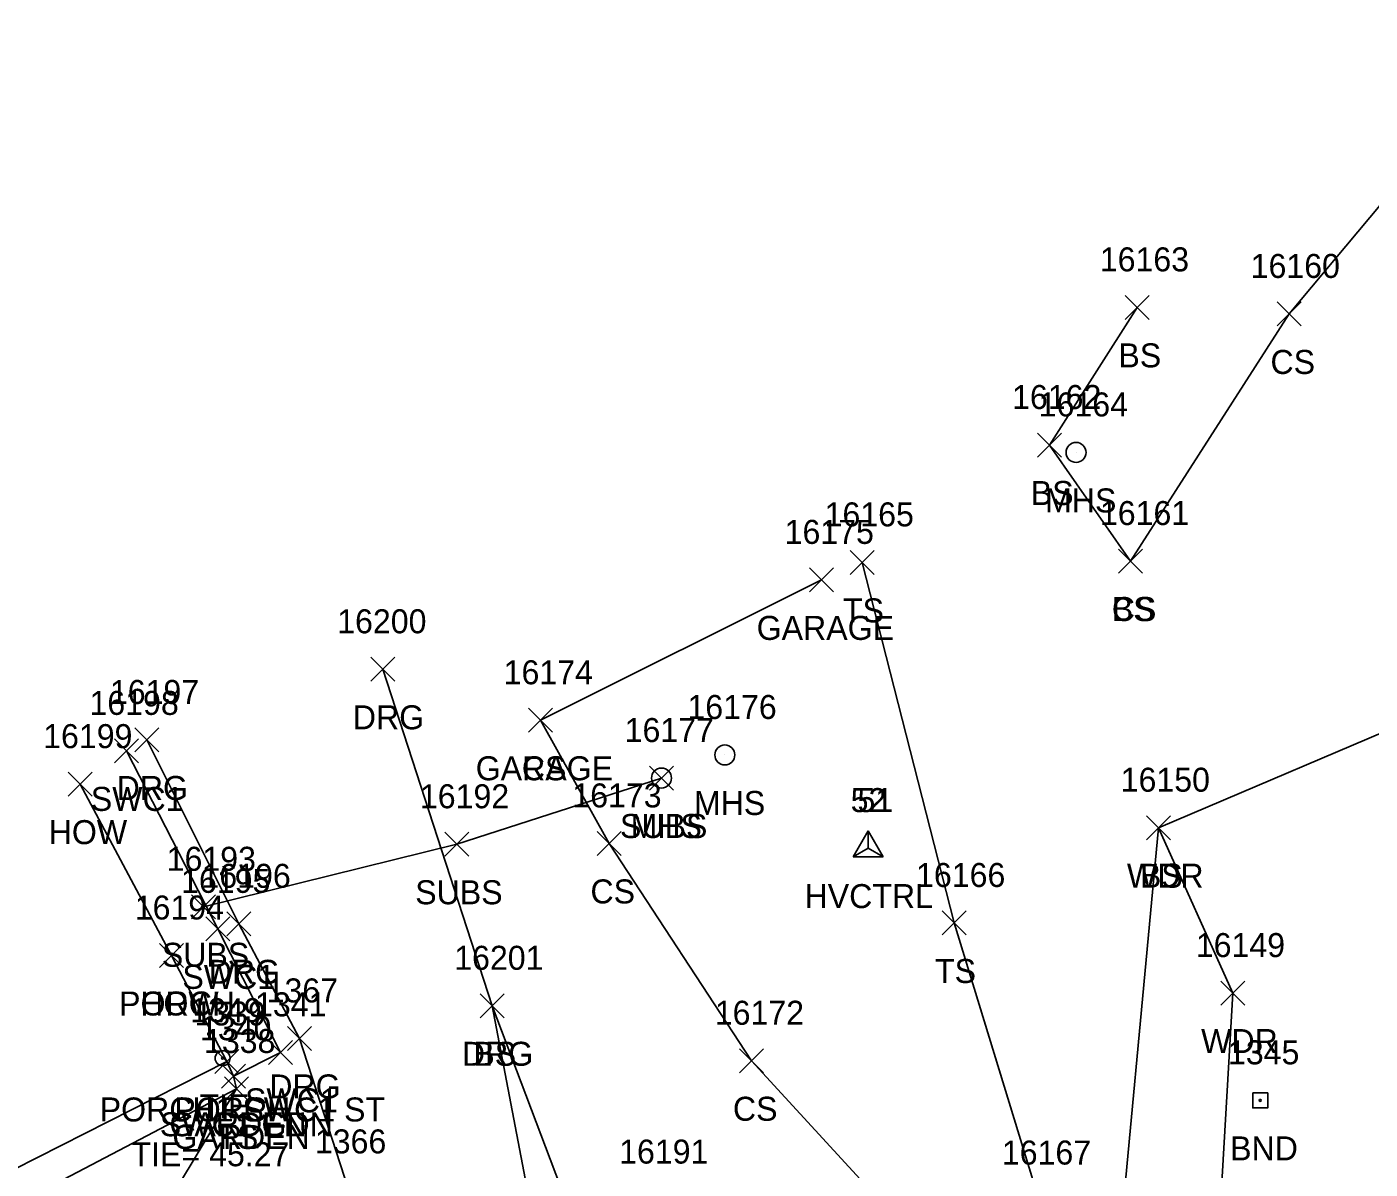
# Model space of a CAD drawing. Extents: x 1606530 to 1613020, y 784959 to 789666.
# Drawn here: x 1609059.8 to 1609171.7, y 788467.6 to 788562.7 of the extents above; entities that cross this region are included whole.
import ezdxf

# ---------------------------------------------------------------- set-up
doc = ezdxf.new("R2010")
doc.units = 0
for name, color, linetype in [('C_A', 7, 'Continuous'), ('C_C', 7, 'Continuous'), ('C_I', 7, 'Continuous'), ('CBP', 7, 'Continuous'), ('CPSM', 7, 'Continuous'), ('L_A', 7, 'Continuous'), ('L_I', 7, 'Continuous'), ('L_TIC', 7, 'Continuous'), ('LAPB', 7, 'Continuous'), ('LAWA', 7, 'Continuous'), ('LBC', 7, 'Continuous'), ('LBF', 7, 'Continuous'), ('LELB', 7, 'Continuous'), ('M_A', 7, 'Continuous'), ('M_I', 7, 'Continuous'), ('MHBP', 7, 'Continuous'), ('R_A', 7, 'Continuous'), ('R_I', 7, 'Continuous'), ('R_TIC', 7, 'Continuous'), ('RDG', 7, 'Continuous'), ('RSW', 7, 'Continuous'), ('U_A', 7, 'Continuous'), ('U_I', 7, 'Continuous'), ('U_TIC', 7, 'Continuous'), ('USA', 7, 'Continuous'), ('USMH', 7, 'Continuous')]:
    doc.layers.add(name, color=color, linetype=linetype)

msp = doc.modelspace()

# ---------------------------------------------------------------- linework, layer by layer
at = {"layer": 'CBP'}
for radius in [0.625, 0.0833]:
    msp.add_circle((1609076.13, 788476.8), radius, dxfattribs=at)
at = {"layer": 'CPSM'}
for p, q in [((1609128.68, 788493.59), (1609129.93, 788495.76)), ((1609128.68, 788493.59), (1609129.93, 788495.75)), ((1609131.18, 788493.59), (1609129.93, 788495.76)), ((1609129.93, 788494.31), (1609129.93, 788495.76)), ((1609131.18, 788493.59), (1609129.93, 788495.75)), ((1609129.93, 788494.31), (1609129.93, 788495.75)), ((1609128.68, 788493.59), (1609129.93, 788494.31)), ((1609128.68, 788493.59), (1609129.93, 788494.31)), ((1609128.68, 788493.59), (1609131.18, 788493.59)), ((1609128.68, 788493.59), (1609131.18, 788493.59)), ((1609129.93, 788494.31), (1609129.93, 788494.31)), ((1609129.93, 788494.31), (1609131.18, 788493.59)), ((1609129.93, 788494.31), (1609129.93, 788494.31)), ((1609129.93, 788494.31), (1609131.18, 788493.59))]:
    msp.add_line(p, q, dxfattribs=at)
at = {"layer": 'L_TIC'}
for points in [[(1609151.33, 788538.37), (1609153.33, 788540.37)], [(1609153.33, 788538.37), (1609151.33, 788540.37)], [(1609164, 788537.82), (1609166, 788539.82)], [(1609166, 788537.82), (1609164, 788539.82)], [(1609144.02, 788526.9), (1609146.02, 788528.9)], [(1609146.02, 788526.9), (1609144.02, 788528.9)], [(1609128.41, 788517.12), (1609130.41, 788519.12)], [(1609130.41, 788517.12), (1609128.41, 788519.12)], [(1609150.78, 788517.23), (1609152.78, 788519.23)], [(1609152.78, 788517.23), (1609150.78, 788519.23)], [(1609150.78, 788517.23), (1609152.78, 788519.23)], [(1609152.78, 788517.23), (1609150.78, 788519.23)], [(1609125.03, 788515.66), (1609127.03, 788517.66)], [(1609127.03, 788515.66), (1609125.03, 788517.66)], [(1609101.62, 788503.96), (1609103.62, 788505.96)], [(1609103.62, 788503.96), (1609101.62, 788505.96)], [(1609101.62, 788503.96), (1609103.62, 788505.96)], [(1609103.62, 788503.96), (1609101.62, 788505.96)], [(1609063.26, 788498.64), (1609065.26, 788500.64)], [(1609065.26, 788498.64), (1609063.26, 788500.64)], [(1609153.12, 788495.01), (1609155.12, 788497.01)], [(1609155.12, 788495.01), (1609153.12, 788497.01)], [(1609153.12, 788495.01), (1609155.12, 788497.01)], [(1609155.12, 788495.01), (1609153.12, 788497.01)], [(1609107.34, 788493.7), (1609109.34, 788495.7)], [(1609109.34, 788493.7), (1609107.34, 788495.7)], [(1609136.08, 788487.07), (1609138.08, 788489.07)], [(1609138.08, 788487.07), (1609136.08, 788489.07)], [(1609070.88, 788484.36), (1609072.88, 788486.36)], [(1609072.88, 788484.36), (1609070.88, 788486.36)], [(1609070.88, 788484.36), (1609072.88, 788486.36)], [(1609072.88, 788484.36), (1609070.88, 788486.36)], [(1609159.3, 788481.23), (1609161.3, 788483.23)], [(1609161.3, 788481.23), (1609159.3, 788483.23)], [(1609097.58, 788480.17), (1609099.58, 788482.17)], [(1609099.58, 788480.17), (1609097.58, 788482.17)], [(1609075.48, 788475.53), (1609077.48, 788477.53)], [(1609077.48, 788475.53), (1609075.48, 788477.53)], [(1609119.21, 788475.59), (1609121.21, 788477.59)], [(1609121.21, 788475.59), (1609119.21, 788477.59)], [(1609076.03, 788474.3), (1609078.03, 788476.3)], [(1609078.03, 788474.3), (1609076.03, 788476.3)], [(1609076.28, 788473.24), (1609078.28, 788475.24)], [(1609078.28, 788473.24), (1609076.28, 788475.24)], [(1609076.28, 788473.24), (1609078.28, 788475.24)], [(1609078.28, 788473.24), (1609076.28, 788475.24)]]:
    msp.add_lwpolyline(points, dxfattribs=at)
at = {"layer": 'LAPB'}
msp.add_lwpolyline([(1609039.19, 788456.56), (1609048.84, 788460.87), (1609049.6, 788459.75), (1609077.28, 788474.24), (1609077.03, 788475.3)], dxfattribs=at)
at = {"layer": 'LAWA'}
msp.add_lwpolyline([(1609458.89, 788516.22), (1609465.52, 788489.74), (1609475.82, 788469.82), (1609458.93, 788473.78), (1609440.54, 788476.41), (1609422.32, 788472.18), (1609400.86, 788472.53), (1609378.74, 788469.08), (1609331.76, 788471.95), (1609305.7, 788472.62), (1609293.07, 788472.82), (1609275.81, 788471.77), (1609233.21, 788467.38), (1609185.7, 788461.65), (1609159.09, 788461.18), (1609160.3, 788482.23), (1609154.12, 788496.01), (1609177.08, 788505.79)], dxfattribs=at)
at = {"layer": 'LBC'}
for points in [[(1609102.62, 788504.96), (1609126.03, 788516.66)], [(1609071.88, 788485.36), (1609064.26, 788499.64)]]:
    msp.add_lwpolyline(points, dxfattribs=at)
at = {"layer": 'LBF'}
msp.add_lwpolyline([(1609047.39, 788465.14), (1609048.84, 788462.52), (1609076.48, 788476.53), (1609071.88, 788485.36)], dxfattribs=at)
at = {"layer": 'LELB'}
for points in [[(1609185.03, 788562.74), (1609165, 788538.82), (1609151.78, 788518.23)], [(1609151.78, 788518.23), (1609145.02, 788527.9), (1609152.33, 788539.37)], [(1609129.41, 788518.12), (1609137.08, 788488.07), (1609144.18, 788464.94), (1609150.24, 788454.68)], [(1609137.67, 788457.57), (1609120.21, 788476.59), (1609108.34, 788494.7), (1609102.62, 788504.96)], [(1609154.12, 788496.01), (1609150.24, 788454.68), (1609137.67, 788457.57), (1609121.95, 788456.07), (1609110.76, 788448.99), (1609098.58, 788481.17)], [(1609023.98, 788453.35), (1609032.54, 788443.85), (1609054.32, 788450.9), (1609067.62, 788458.19), (1609077.28, 788474.24)]]:
    msp.add_lwpolyline(points, dxfattribs=at)
at = {"layer": 'MHBP'}
msp.add_lwpolyline([(1609161.97, 788473.91), (1609163.22, 788473.91), (1609163.22, 788472.66), (1609161.97, 788472.66)], close=True, dxfattribs=at)
msp.add_circle((1609162.59, 788473.29), 0.0833, dxfattribs=at)
at = {"layer": 'R_TIC'}
for points in [[(1609088.49, 788508.21), (1609090.49, 788510.21)], [(1609090.49, 788508.21), (1609088.49, 788510.21)], [(1609068.82, 788502.32), (1609070.82, 788504.32)], [(1609070.82, 788502.32), (1609068.82, 788504.32)], [(1609067.11, 788501.41), (1609069.11, 788503.41)], [(1609069.11, 788501.41), (1609067.11, 788503.41)], [(1609074.74, 788486.58), (1609076.74, 788488.58)], [(1609076.74, 788486.58), (1609074.74, 788488.58)], [(1609076.49, 788487), (1609078.49, 788489)], [(1609078.49, 788487), (1609076.49, 788489)], [(1609097.58, 788480.17), (1609099.58, 788482.17)], [(1609099.58, 788480.17), (1609097.58, 788482.17)], [(1609081.54, 788477.45), (1609083.54, 788479.45)], [(1609083.54, 788477.45), (1609081.54, 788479.45)], [(1609079.96, 788476.29), (1609081.96, 788478.29)], [(1609081.96, 788476.29), (1609079.96, 788478.29)], [(1609075.48, 788475.53), (1609077.48, 788477.53)], [(1609077.48, 788475.53), (1609075.48, 788477.53)], [(1609076.03, 788474.3), (1609078.03, 788476.3)], [(1609078.03, 788474.3), (1609076.03, 788476.3)]]:
    msp.add_lwpolyline(points, dxfattribs=at)
at = {"layer": 'RDG'}
for points in [[(1609089.49, 788509.21), (1609098.58, 788481.17), (1609104.12, 788452.24), (1609106.36, 788443.93), (1609109.47, 788440.87), (1609110.72, 788439.13)], [(1609089.85, 788433.28), (1609091.73, 788441.2), (1609090.79, 788449.89), (1609086.62, 788465.87), (1609082.54, 788478.45), (1609077.49, 788488), (1609069.82, 788503.32)]]:
    msp.add_lwpolyline(points, dxfattribs=at)
at = {"layer": 'RSW'}
msp.add_lwpolyline([(1609076.48, 788476.53), (1609077.03, 788475.3), (1609080.96, 788477.29), (1609075.74, 788487.58), (1609068.11, 788502.41)], dxfattribs=at)
at = {"layer": 'U_TIC'}
for points in [[(1609111.7, 788499.15), (1609113.7, 788501.15)], [(1609113.7, 788499.15), (1609111.7, 788501.15)], [(1609094.64, 788493.63), (1609096.64, 788495.63)], [(1609096.64, 788493.63), (1609094.64, 788495.63)], [(1609073.54, 788488.42), (1609075.54, 788490.42)], [(1609075.54, 788488.42), (1609073.54, 788490.42)]]:
    msp.add_lwpolyline(points, dxfattribs=at)
at = {"layer": 'USA'}
msp.add_lwpolyline([(1609112.7, 788500.15), (1609095.64, 788494.63), (1609074.54, 788489.42)], dxfattribs=at)
at = {"layer": 'USMH'}
for p, q in [((1609147.24, 788527.28), (1609147.24, 788527.28)), ((1609148.08, 788527.28), (1609148.08, 788527.28)), ((1609117.98, 788502.07), (1609117.98, 788502.07)), ((1609118.81, 788502.07), (1609118.81, 788502.07)), ((1609112.7, 788500.15), (1609112.7, 788500.15)), ((1609113.53, 788500.15), (1609113.53, 788500.15))]:
    msp.add_line(p, q, dxfattribs=at)
for centre in [(1609147.24, 788527.28), (1609117.98, 788502.07), (1609112.7, 788500.15)]:
    msp.add_circle(centre, 0.833, dxfattribs=at)

# ---------------------------------------------------------------- texts
at = {"layer": 'C_A'}
for s, p in [('HVCTRL', (1609124.62, 788489.31)), ('HVCTRL', (1609124.62, 788489.31)), ('TIE', (1609074.21, 788471.8))]:
    msp.add_text(s, height=2, dxfattribs=at).set_placement(p)
at = {"layer": 'C_C'}
msp.add_text('TIE= 45.27', height=2, dxfattribs=at).set_placement((1609068.54, 788467.8))
at = {"layer": 'C_I'}
for s, p in [('52', (1609128.46, 788497.31)), ('51', (1609129.03, 788497.31)), ('1349', (1609073.43, 788479.8))]:
    msp.add_text(s, height=2, dxfattribs=at).set_placement(p)
at = {"layer": 'L_A'}
for s, p in [('BS', (1609150.77, 788534.37)), ('CS', (1609163.44, 788533.82)), ('BS', (1609143.47, 788522.9)), ('TS', (1609127.82, 788513.12)), ('CS', (1609150.22, 788513.23)), ('BS', (1609150.22, 788513.23)), ('GARAGE', (1609120.63, 788511.66)), ('GARAGE', (1609097.22, 788499.96)), ('CS', (1609101.06, 788499.96)), ('HOW', (1609061.64, 788494.64)), ('WDR', (1609151.48, 788491.01)), ('BS', (1609152.56, 788491.01)), ('CS', (1609106.78, 788489.7)), ('TS', (1609135.49, 788483.07)), ('PORCH', (1609067.51, 788480.36)), ('HOW', (1609069.27, 788480.36)), ('WDR', (1609157.66, 788477.23)), ('BS', (1609097.02, 788476.17)), ('PORCH', (1609072.11, 788471.53)), ('CS', (1609118.65, 788471.59)), ('GARDEN', (1609071.7, 788470.3)), ('GARDEN', (1609071.95, 788469.24)), ('TS', (1609075.69, 788469.24))]:
    msp.add_text(s, height=2, dxfattribs=at).set_placement(p)
at = {"layer": 'L_I'}
for s, p in [('16163', (1609149.22, 788542.37)), ('16160', (1609161.79, 788541.82)), ('16162', (1609141.91, 788530.9)), ('16165', (1609126.29, 788521.12)), ('16161', (1609149.23, 788521.23)), ('16161', (1609149.23, 788521.23)), ('16175', (1609122.96, 788519.66)), ('16174', (1609099.55, 788507.96)), ('16174', (1609099.55, 788507.96)), ('16199', (1609061.18, 788502.64)), ('16150', (1609150.96, 788499.01)), ('16150', (1609150.96, 788499.01)), ('16173', (1609105.27, 788497.7)), ('16166', (1609133.91, 788491.07)), ('16194', (1609068.81, 788488.36)), ('16194', (1609068.81, 788488.36)), ('16149', (1609157.22, 788485.23)), ('16201', (1609095.43, 788484.17)), ('1339', (1609073.78, 788479.53)), ('16172', (1609117.14, 788479.59)), ('1340', (1609074.25, 788478.3)), ('1338', (1609074.58, 788477.24)), ('1338', (1609074.58, 788477.24)), ('1366', (1609083.82, 788468.87)), ('16191', (1609109.17, 788468.02)), ('16167', (1609141.06, 788467.94))]:
    msp.add_text(s, height=2, dxfattribs=at).set_placement(p)
at = {"layer": 'M_A'}
msp.add_text('BND', height=2, dxfattribs=at).set_placement((1609160.08, 788468.29))
at = {"layer": 'M_I'}
msp.add_text('1345', height=2, dxfattribs=at).set_placement((1609159.9, 788476.29))
at = {"layer": 'R_A'}
for s, p in [('DRG', (1609086.98, 788504.21)), ('DRG', (1609067.3, 788498.32)), ('SWC1', (1609065.15, 788497.41)), ('SWC1', (1609072.78, 788482.58)), ('DRG', (1609074.98, 788483)), ('DRG', (1609096.07, 788476.17)), ('DRG', (1609080.02, 788473.45)), ('PORCH1 SWC1 ST', (1609065.89, 788471.53)), ('SWC1', (1609078, 788472.29)), ('SWC1 GDN', (1609070.9, 788470.3))]:
    msp.add_text(s, height=2, dxfattribs=at).set_placement(p)
at = {"layer": 'R_I'}
for s, p in [('16200', (1609085.68, 788512.21)), ('16197', (1609066.74, 788506.32)), ('16198', (1609065.04, 788505.41)), ('16195', (1609072.67, 788490.58)), ('16196', (1609074.37, 788491)), ('16201', (1609095.43, 788484.17)), ('1367', (1609079.8, 788481.45)), ('1339', (1609073.78, 788479.53)), ('1341', (1609078.83, 788480.29)), ('1340', (1609074.25, 788478.3)), ('1366', (1609083.82, 788468.87))]:
    msp.add_text(s, height=2, dxfattribs=at).set_placement(p)
at = {"layer": 'U_A'}
for s, p in [('MHS', (1609144.66, 788522.28)), ('MHS', (1609115.4, 788497.07)), ('SUBS', (1609109.24, 788495.15)), ('MHS', (1609110.12, 788495.15)), ('SUBS', (1609092.18, 788489.63)), ('SUBS', (1609071.07, 788484.42))]:
    msp.add_text(s, height=2, dxfattribs=at).set_placement(p)
at = {"layer": 'U_I'}
for s, p in [('16164', (1609144.13, 788530.28)), ('16176', (1609114.86, 788505.07)), ('16177', (1609109.63, 788503.15)), ('16177', (1609109.63, 788503.15)), ('16192', (1609092.57, 788497.63)), ('16193', (1609071.47, 788492.42))]:
    msp.add_text(s, height=2, dxfattribs=at).set_placement(p)

doc.saveas('drawing.dxf')
